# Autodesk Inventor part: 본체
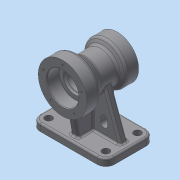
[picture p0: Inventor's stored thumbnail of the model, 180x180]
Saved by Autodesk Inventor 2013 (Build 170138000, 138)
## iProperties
Created: 2015-08
Part Number: 본체
Material: 일반
Document SubType Name: Modeling
Designer: Administrator
Density: 1 g/cm^3
Author: Administrator
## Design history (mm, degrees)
sketch "스케치2"
  geometry: L1 (-61, 40)-(61, 40); L2 (61, 40)-(61, -40); L3 (61, -40)-(-61, -40); L4 (-61, -40)-(-61, 40); L5 (-61, 40)-(61, -40); L6 (61, 40)-(-61, -40); 1 further point
  constraints: 12 end point, 2 midpoint, 2 parallel, 1 horizontal, 1 perpendicular
  dimensions: "d0" = 122 distance of L2.end L3.end; "d1" = 80 distance of L1.end L2.end
extrude "돌출1" new body sketch "스케치2" distance "d2" = 12; taper "d3" = 0 deg
sketch "스케치4"
  geometry: L1 (90, 50)-(90, -40); L2 (0, -40)-(0, 40) reference; L3 (90, 50)-(130, 50); L4 (130, 50)-(130, 30); L5 (130, 30)-(116, 13.315); L6 (116, 13.315)-(116, -14.804); L7 (116, -14.804)-(125, -20); L8 (125, -20)-(125, -40); L9 (125, -40)-(90, -40); L10 (0, 40)-(12, 40) reference; L11 (0, -40)-(12, -40) reference; 2 further points
  constraints: 16 end point, 3 parallel, 2 perpendicular, 1 midpoint, 1 vertical
  dimensions: "d29" = 90 distance between parallel lines of L2 L1; "d30" = 80 diameter of L4 L1; "d31" = 52 diameter of L6 L1; "d32" = 70 diameter of L8 L1; "d33" = 20 distance of L3.end L4.end; "d34" = 20 distance of L7.end L8.end; "d35" = 40 deg angle of L6 L5; "d36" = 60 deg angle of L6 L7; "d37" = 90 distance between parallel lines of L9 L3; "d123" = 0 distance between parallel lines of L9 L11
revolve "회전1" sketch "스케치4" stored, may be unused: angle "d38" = 90 deg
sketch "스케치5"
  geometry: C1 r 40 at (0, 0) reference; C2 r 26 at (0, 0); 1 further point
  constraints: 1 centre point, 1 coincident
  dimensions: "d39" = 52 diameter of C2
extrude "돌출2" cut sketch "스케치5" distance "d40" = 20; taper "d41" = 0 deg
sketch "스케치6"
  geometry: C1 r 26 at (0, 0) reference; C2 r 19 at (0, 0); 1 further point
  constraints: 1 centre point, 1 coincident
  dimensions: "d42" = 38 diameter of C2
extrude "돌출3" cut sketch "스케치6" distance "d43" = 3; taper "d44" = 0 deg
sketch "스케치7"
  geometry: C1 r 19 at (0, 0) reference; C2 r 16 at (0, 0); 1 further point
  constraints: 1 centre point, 1 coincident
  dimensions: "d45" = 32 diameter of C2
extrude "돌출4" cut sketch "스케치7" stored distance "d46" = 3; taper "d47" = 0 deg
sketch "스케치8"
  geometry: C1 r 16 at (0, 0) reference; C2 r 35 at (0, 0) reference; C3 r 20 at (0, 0); 1 further point
  constraints: 1 centre point, 1 coincident
  dimensions: "d48" = 40 diameter of C3
extrude "돌출5" cut sketch "스케치8" distance "d49" = 17; taper "d50" = 0 deg
sketch "스케치9"
  geometry: L1 (64, -14.804)-(116, -14.804) reference; L2 (64, 13.315)-(116, 13.315) reference; L3 (7.99, -30)-(62.455, -30); L4 (0, -40)-(12, -40) reference; L5 (0, 40)-(12, 40) reference; L6 (62.543, 38.912)-(12, 30); L7 (12, -40)-(12, 40) reference; L8 (12, 30)-(4.609, 30); L9 (4.609, 30)-(4.609, -30); L10 (4.609, -30)-(7.99, -30); L11 (62.543, 38.912)-(62.543, 30.118); L12 (62.543, 30.118)-(71.523, 23.298); L13 (71.523, 23.298)-(71.523, -18.06); L14 (71.523, -18.06)-(62.455, -30)
  constraints: 18 end point, 5 perpendicular, 2 parallel
  dimensions: "d124" = 10 distance between parallel lines of L4 L3; "d126" = 10 distance from line of L6.end L5; "d127" = 80 deg angle of L6 L7
extrude "돌출6" join sketch "스케치9" stored distance "d56" = 12; taper "d57" = 0 deg
sketch "스케치10"
  geometry: L1 (61, 12)-(61, 0) reference; L2 (61, 0)-(-61, 0) reference; L3 (-61, 0)-(-61, 12) reference; L4 (-61, 12)-(-6, 12) reference; L5 (-6, 12)-(-6, 64.702) reference; L6 (6, 64.702)-(6, 12) reference; L7 (6, 12)-(61, 12) reference; L8 (-51, 12)-(-25.091, 83.185); L9 (-6, 64.702)-(-6, 12); L10 (-51, 12)-(-6, 12); L11 (51, 12)-(25.091, 83.185); L12 (6, 64.702)-(6, 12); L13 (51, 12)-(6, 12); C1 r 16 at (0, 90) reference; A1 r 26 centre (0, 90) between (6, 64.702) and (-6, 64.702) reference; A2 r 26 centre (0, 90) between (-25.091, 83.185) and (-6, 64.702); A3 r 26 centre (0, 90) between (6, 64.702) and (25.091, 83.185); 1 further point
  constraints: 13 end point, 4 point on circle, 2 centre point, 2 collinear, 2 point on line, 1 coincident
  dimensions: "d58" = 10 distance from line of L8.start L3; "d59" = 70 deg angle of L4 L8
extrude "돌출7" join sketch "스케치10" stored distance "d60" = 12; taper "d61" = 0 deg
sketch "스케치11"
  geometry: C1 r 6 at (-47, 26); C2 r 6 at (47, 26); C3 r 6 at (-47, -26); C4 r 6 at (47, -26); 1 further point
  constraints: 4 centre point
  dimensions: "d62" = 12 diameter of C1; "d63" = 12 diameter of C2; "d64" = 12 diameter of C3; "d65" = 12 diameter of C4; "d66" = 94 distance of C2.centre C1.centre; "d67" = 94 distance of C4.centre C3.centre; "d68" = 52 distance of C3.centre C1.centre; "d69" = 26 vertical distance of point (0, 0) C1.centre; "d70" = 47 horizontal distance of point (0, 0) C1.centre; "d71" = 52 distance of C4.centre C2.centre; "d72" = 26 vertical distance of point (0, 0) C2.centre; "d73" = 47 horizontal distance of point (0, 0) C3.centre
extrude "돌출8" cut sketch "스케치11" stored distance "d74" = 12; taper "d75" = 0 deg
sketch "스케치12"
  geometry: 2 further points
hole "구멍1" sketch "스케치12" at (0, 33) diameter "d77" = 3.242; stored, may be unused: countersink angle "d81" = 90 deg, drill point angle "d83" = 118 deg; dims "d78" = 10, "d79" = 4, "d80" = 2, "d82" = 13
sketch "스케치13"
  geometry: 2 further points
hole "구멍2" sketch "스케치13" at (0, 27) diameter "d88" = 3.242; stored, may be unused: countersink angle "d92" = 90 deg, drill point angle "d94" = 118 deg; dims "d89" = 10, "d90" = 4, "d91" = 2, "d93" = 13
fillet "모깎기2" dims "d99" = 0.3
fillet "모깎기3" dims "d100" = 14
sketch "스케치14"
  geometry: L1 (51, 12)-(6, 12) reference; L2 (51, 12)-(25.091, 83.185) reference; L3 (6, 12)-(6, 64.702) reference; L4 (47, 0)-(-47, 0) reference; L5 (-24, 42)-(-24, 42); L6 (-18, 36)-(-18, 30); L7 (-24, 24)-(-24, 24); L8 (-30, 30)-(-30, 36); L9 (24, 42)-(24, 42); L10 (30, 36)-(30, 30); L11 (24, 24)-(24, 24); L12 (18, 30)-(18, 36); A1 r 26 centre (0, 90) between (6, 64.702) and (25.091, 83.185) reference; A2 r 6 centre (-24, 36) between (-24, 42) and (-30, 36); A3 r 6 centre (-24, 36) between (-18, 36) and (-24, 42); A4 r 6 centre (-24, 30) between (-30, 30) and (-24, 24); A5 r 6 centre (-24, 30) between (-24, 24) and (-18, 30); A6 r 6 centre (24, 36) between (24, 42) and (18, 36); A7 r 6 centre (24, 36) between (30, 36) and (24, 42); A8 r 6 centre (24, 30) between (24, 24) and (30, 30); A9 r 6 centre (24, 30) between (18, 30) and (24, 24); 7 further points
  constraints: 16 end point, 16 point on circle, 16 tangent, 12 point on line, 8 centre point, 7 equal radius, 4 parallel, 2 horizontal, 2 perpendicular
  dimensions: "d105" = 12 distance of point (-30, 42) point (-18, 42); "d106" = 18 distance of point (-30, 24) point (-30, 42); "d107" = 12 distance of point (18, 42) point (30, 42); "d108" = 18 distance of point (30, 42) point (30, 24); "d111" = 60 distance between parallel lines of L10 L8; "d112" = 30 distance from line of point (0, 0) L8; "d113" = 6 radius of A2
extrude "돌출9" cut sketch "스케치14" stored distance "d114" = 12; taper "d115" = 0 deg
fillet "모깎기5" dims "d117" = 3
chamfer "모따기1" distance "d119" = 1; stored, may be unused: second distance "d120" = 2, angle "d121" = 45 deg
fillet "모깎기7" dims "d122" = 3
fillet "모깎기9" dims "d129" = 3
fillet "모깎기10" dims "d130" = 3
fillet "모깎기12" dims "d132" = 5
fillet "모깎기13" dims "d133" = 3
fillet "모깎기14" dims "d134" = 3
fillet "모깎기15" dims "d135" = 3
fillet "모깎기16" dims "d136" = 3
sketch "스케치15"
  geometry: L1 (-37, 12)-(-26, 12) reference; L2 (-30, 52.119)-(-30, 15) reference; 2 further points
  constraints: 1 other
  dimensions: "d137" = 24 distance from line of L1 point (-14, 36); "d138" = 16 distance from line of point (-14, 36) L2
feature "엠보싱1" sketch "스케치15" dims "d0" = 122, "d1" = 80, "d139" = 0.5, "d140" = 0
node "솔리드1"
pattern_circular "원형 패턴1" dims angle "d85" = 360 deg
pattern_circular "원형 패턴2" dims angle "d96" = 360 deg
node "투영된 루프1"
node "투영된 루프2"
node "절단 모서리 투영1"
